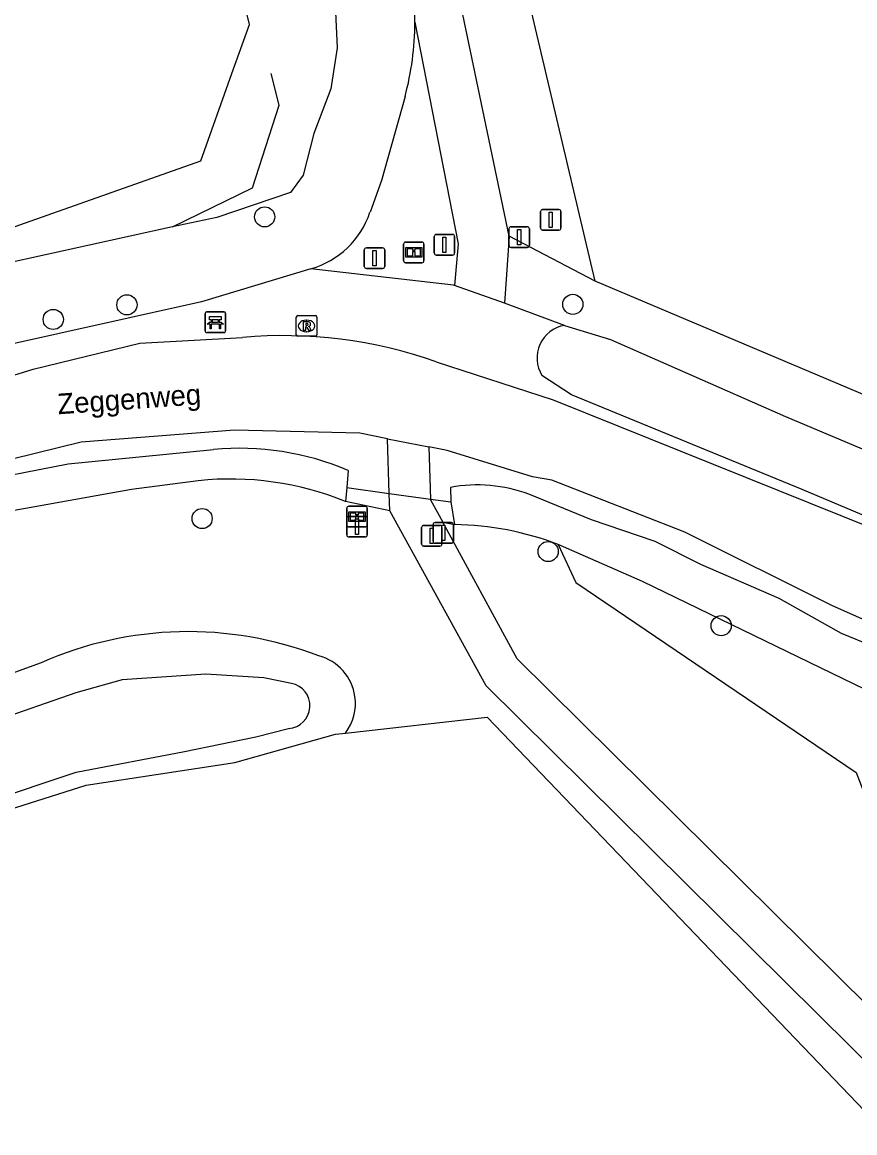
# Model space of a CAD drawing. Extents: x 164494 to 166241, y 382475 to 384494.
# Drawn here: x 164923.4 to 164963.8, y 383448.6 to 383502.5 of the extents above; entities that cross this region are included whole.
import ezdxf

# ---------------------------------------------------------------- set-up
doc = ezdxf.new("R2010")
doc.units = 0
for name, color, linetype in [('IMGEO_Afsluitpaal', 7, 'Continuous'), ('IMGEO_Bank', 7, 'Continuous'), ('IMGEO_Boom', 7, 'Continuous'), ('IMGEO_Bouwland', 7, 'Continuous'), ('IMGEO_Duiker', 7, 'Continuous'), ('IMGEO_Grasland_overig', 7, 'Continuous'), ('IMGEO_Groenvoorziening', 7, 'Continuous'), ('IMGEO_Hek', 7, 'Continuous'), ('IMGEO_Informatiebord', 7, 'Continuous'), ('IMGEO_Loofbos', 7, 'Continuous'), ('IMGEO_Openbare_ruimte_label', 7, 'Continuous'), ('IMGEO_Rijbaan_lokaal_halfverhard', 7, 'Continuous'), ('IMGEO_Rioolput', 7, 'Continuous'), ('IMGEO_Waterloop', 7, 'Continuous')]:
    doc.layers.add(name, color=color, linetype=linetype)

msp = doc.modelspace()

# ---------------------------------------------------------------- linework, layer by layer
at = {"layer": 'IMGEO_Afsluitpaal'}
for p, q in [((164948.533, 383492.504), (164948.533, 383493.304)), ((164948.533, 383493.304), (164948.533, 383492.504)), ((164948.633, 383493.404), (164949.423, 383493.404)), ((164949.423, 383493.404), (164948.633, 383493.404)), ((164949.523, 383493.304), (164949.523, 383492.504)), ((164949.523, 383492.504), (164949.523, 383493.304)), ((164946.998, 383491.666), (164946.998, 383492.466)), ((164946.998, 383492.466), (164946.998, 383491.666)), ((164947.098, 383492.566), (164947.888, 383492.566)), ((164947.888, 383492.566), (164947.098, 383492.566)), ((164947.988, 383492.466), (164947.988, 383491.666)), ((164947.988, 383491.666), (164947.988, 383492.466)), ((164949.423, 383492.404), (164948.633, 383492.404)), ((164948.633, 383492.404), (164949.423, 383492.404)), ((164943.37, 383491.294), (164943.37, 383492.094)), ((164943.37, 383492.094), (164943.37, 383491.294)), ((164943.47, 383492.194), (164944.26, 383492.194)), ((164944.26, 383492.194), (164943.47, 383492.194)), ((164944.36, 383492.094), (164944.36, 383491.294)), ((164944.36, 383491.294), (164944.36, 383492.094)), ((164939.975, 383490.643), (164939.975, 383491.443)), ((164939.975, 383491.443), (164939.975, 383490.643)), ((164940.075, 383491.543), (164940.865, 383491.543)), ((164940.865, 383491.543), (164940.075, 383491.543)), ((164940.965, 383491.443), (164940.965, 383490.643)), ((164940.965, 383490.643), (164940.965, 383491.443)), ((164947.888, 383491.566), (164947.098, 383491.566)), ((164947.098, 383491.566), (164947.888, 383491.566)), ((164944.26, 383491.194), (164943.47, 383491.194)), ((164943.47, 383491.194), (164944.26, 383491.194)), ((164940.865, 383490.543), (164940.075, 383490.543)), ((164940.075, 383490.543), (164940.865, 383490.543)), ((164939.126, 383477.607), (164939.126, 383478.407)), ((164939.126, 383478.407), (164939.126, 383477.607)), ((164939.226, 383478.507), (164940.016, 383478.507)), ((164940.016, 383478.507), (164939.226, 383478.507)), ((164940.116, 383478.407), (164940.116, 383477.607)), ((164940.116, 383477.607), (164940.116, 383478.407)), ((164942.754, 383477.165), (164942.754, 383477.965)), ((164942.754, 383477.965), (164942.754, 383477.165)), ((164942.854, 383478.065), (164943.644, 383478.065)), ((164943.644, 383478.065), (164942.854, 383478.065)), ((164943.312, 383477.305), (164943.312, 383478.105)), ((164943.312, 383478.105), (164943.312, 383477.305)), ((164943.412, 383478.205), (164944.202, 383478.205)), ((164944.202, 383478.205), (164943.412, 383478.205)), ((164943.744, 383477.965), (164943.744, 383477.165)), ((164943.744, 383477.165), (164943.744, 383477.965)), ((164944.302, 383478.105), (164944.302, 383477.305)), ((164944.302, 383477.305), (164944.302, 383478.105)), ((164940.016, 383477.507), (164939.226, 383477.507)), ((164939.226, 383477.507), (164940.016, 383477.507)), ((164943.644, 383477.065), (164942.854, 383477.065)), ((164942.854, 383477.065), (164943.644, 383477.065)), ((164944.202, 383477.205), (164943.412, 383477.205)), ((164943.412, 383477.205), (164944.202, 383477.205))]:
    msp.add_line(p, q, dxfattribs=at)
for points in [[(164948.953, 383493.279), (164949.103, 383493.279), (164949.103, 383492.529), (164948.953, 383492.529), (164948.953, 383493.279)], [(164947.418, 383492.441), (164947.568, 383492.441), (164947.568, 383491.691), (164947.418, 383491.691), (164947.418, 383492.441)], [(164943.79, 383492.069), (164943.94, 383492.069), (164943.94, 383491.319), (164943.79, 383491.319), (164943.79, 383492.069)], [(164940.395, 383491.418), (164940.545, 383491.418), (164940.545, 383490.668), (164940.395, 383490.668), (164940.395, 383491.418)], [(164939.546, 383478.382), (164939.696, 383478.382), (164939.696, 383477.632), (164939.546, 383477.632), (164939.546, 383478.382)], [(164943.174, 383477.94), (164943.324, 383477.94), (164943.324, 383477.19), (164943.174, 383477.19), (164943.174, 383477.94)], [(164943.732, 383478.08), (164943.882, 383478.08), (164943.882, 383477.33), (164943.732, 383477.33), (164943.732, 383478.08)]]:
    msp.add_lwpolyline(points, dxfattribs=at)
for centre, start, end in [((164948.633, 383493.304), 90, 180), ((164948.633, 383493.304), 90, 180), ((164949.423, 383493.304), 0, 90), ((164949.423, 383493.304), 360, 90), ((164947.098, 383492.466), 90, 180), ((164947.098, 383492.466), 90, 180), ((164947.888, 383492.466), 0, 90), ((164947.888, 383492.466), 360, 90), ((164948.633, 383492.504), 180, 270), ((164948.633, 383492.504), 180, 270), ((164949.423, 383492.504), 270, 0), ((164949.423, 383492.504), 270, 0), ((164943.47, 383492.094), 90, 180), ((164943.47, 383492.094), 90, 180), ((164944.26, 383492.094), 0, 90), ((164944.26, 383492.094), 360, 90), ((164940.075, 383491.443), 90, 180), ((164940.075, 383491.443), 90, 180), ((164940.865, 383491.443), 0, 90), ((164940.865, 383491.443), 360, 90), ((164943.47, 383491.294), 180, 270), ((164943.47, 383491.294), 180, 270), ((164944.26, 383491.294), 270, 0), ((164944.26, 383491.294), 270, 0), ((164947.098, 383491.666), 180, 270), ((164947.098, 383491.666), 180, 270), ((164947.888, 383491.666), 270, 0), ((164947.888, 383491.666), 270, 0), ((164940.075, 383490.643), 180, 270), ((164940.075, 383490.643), 180, 270), ((164940.865, 383490.643), 270, 0), ((164940.865, 383490.643), 270, 0), ((164939.226, 383478.407), 90, 180), ((164939.226, 383478.407), 90, 180), ((164940.016, 383478.407), 0, 90), ((164940.016, 383478.407), 360, 90), ((164942.854, 383477.965), 90, 180), ((164942.854, 383477.965), 90, 180), ((164943.412, 383478.105), 90, 180), ((164943.412, 383478.105), 90, 180), ((164943.644, 383477.965), 0, 90), ((164943.644, 383477.965), 360, 90), ((164944.202, 383478.105), 0, 90), ((164944.202, 383478.105), 360, 90), ((164939.226, 383477.607), 180, 270), ((164939.226, 383477.607), 180, 270), ((164940.016, 383477.607), 270, 0), ((164940.016, 383477.607), 270, 0), ((164943.412, 383477.305), 180, 270), ((164943.412, 383477.305), 180, 270), ((164944.202, 383477.305), 270, 0), ((164944.202, 383477.305), 270, 0), ((164942.854, 383477.165), 180, 270), ((164942.854, 383477.165), 180, 270), ((164943.644, 383477.165), 270, 0), ((164943.644, 383477.165), 270, 0)]:
    msp.add_arc(centre, 0.1, start, end, dxfattribs=at)
at = {"layer": 'IMGEO_Bank'}
for p, q in [((164932.241, 383487.508), (164932.241, 383488.349)), ((164932.241, 383488.349), (164932.241, 383487.508)), ((164932.316, 383488.433), (164933.157, 383488.433)), ((164933.157, 383488.433), (164932.316, 383488.433)), ((164933.241, 383488.358), (164933.241, 383487.517)), ((164933.241, 383487.517), (164933.241, 383488.358)), ((164932.938, 383487.831), (164932.545, 383487.831)), ((164932.55, 383487.939), (164932.55, 383488.045)), ((164932.594, 383488.045), (164932.594, 383487.939)), ((164932.882, 383488.051), (164932.6, 383488.051)), ((164932.6, 383487.933), (164932.882, 383487.933)), ((164932.888, 383487.939), (164932.888, 383488.045)), ((164932.932, 383488.045), (164932.932, 383487.939)), ((164933.166, 383487.433), (164932.325, 383487.433)), ((164932.325, 383487.433), (164933.166, 383487.433))]:
    msp.add_line(p, q, dxfattribs=at)
for points in [[(164932.544, 383488.051), (164932.458, 383488.051), (164932.458, 383488.212), (164933.021, 383488.212), (164933.021, 383488.051), (164932.938, 383488.051)], [(164932.488, 383487.831), (164932.346, 383487.831), (164932.458, 383487.933), (164932.544, 383487.933)], [(164932.538, 383487.824), (164932.538, 383487.617), (164932.495, 383487.617), (164932.495, 383487.824)], [(164932.938, 383487.933), (164933.021, 383487.933), (164933.133, 383487.831), (164932.994, 383487.831)], [(164932.988, 383487.824), (164932.988, 383487.617), (164932.944, 383487.617), (164932.944, 383487.824)]]:
    msp.add_lwpolyline(points, dxfattribs=at)
for centre, radius, start, end in [((164932.319, 383488.355), 0.0779, 92.4484, 184.2845), ((164932.319, 383488.355), 0.0779, 92.4484, 184.2845), ((164933.163, 383488.355), 0.0779, 2.4484, 94.2845), ((164933.163, 383488.355), 0.0779, 2.4484, 94.2845), ((164932.488, 383487.824), 0.00671, 2.8957, 87.1043), ((164932.545, 383487.824), 0.00671, 92.8957, 177.1043), ((164932.543, 383488.044), 0.00671, 2.8957, 87.1043), ((164932.543, 383487.94), 0.00671, 272.8957, 357.1043), ((164932.6, 383488.044), 0.00671, 92.8957, 177.1043), ((164932.6, 383487.94), 0.00671, 182.8957, 267.1043), ((164932.882, 383488.044), 0.00671, 2.8957, 87.1043), ((164932.882, 383487.94), 0.00671, 272.8957, 357.1043), ((164932.939, 383488.044), 0.00671, 92.8957, 177.1043), ((164932.939, 383487.94), 0.00671, 182.8957, 267.1043), ((164932.937, 383487.824), 0.00671, 2.8957, 87.1043), ((164932.994, 383487.824), 0.00671, 92.8957, 177.1043), ((164933.163, 383487.511), 0.0779, 272.4484, 4.2845), ((164933.163, 383487.511), 0.0779, 272.4484, 4.2845), ((164932.319, 383487.511), 0.0779, 182.4484, 274.2845), ((164932.319, 383487.511), 0.0779, 182.4484, 274.2845)]:
    msp.add_arc(centre, radius, start, end, dxfattribs=at)
at = {"layer": 'IMGEO_Boom'}
for centre in [(164935.137, 383493.047), (164928.449, 383488.778), (164950.1, 383488.8), (164924.872, 383488.067), (164932.1, 383478.4), (164948.9, 383476.8), (164957.3, 383473.2)]:
    msp.add_circle(centre, 0.489, dxfattribs=at)
at = {"layer": 'IMGEO_Bouwland'}
msp.add_lwpolyline([(164912.566, 383384.323), (164876.262, 383433.486), (164868.931, 383444.423), (164868.575, 383444.955), (164910.854, 383460.501), (164926.474, 383465.463), (164933.685, 383466.564), (164938.58, 383467.935), (164939.064, 383467.989)], dxfattribs=at)
at = {"layer": 'IMGEO_Duiker'}
msp.add_lwpolyline([(164939.126, 383479.906), (164941.181, 383479.625), (164943.19, 383479.35), (164944.181, 383479.214)], dxfattribs=at)
at = {"layer": 'IMGEO_Grasland_overig'}
for points in [[(164947.002, 383492.109), (164934.899, 383550.036), (164933.532, 383554.465)], [(164942.432, 383502.496), (164944.525, 383491.737), (164944.349, 383489.717)], [(164947.002, 383492.109), (164946.787, 383488.862)], [(164946.787, 383488.862), (164944.349, 383489.717)], [(164941.206, 383478.776), (164941.181, 383479.625), (164941.103, 383482.279)], [(164943.115, 383481.884), (164943.19, 383479.35), (164943.191, 383479.313), (164943.78, 383478.232)], [(164941.206, 383478.776), (164939.069, 383479.227)], [(165072.749, 383381.958), (165062.554, 383397.301), (165051.511, 383396.474), (165026.953, 383397.574), (165014.572, 383404.259), (164992.612, 383424.036), (164945.886, 383470.277), (164941.206, 383478.776)], [(165000.271, 383419.83), (164993.985, 383425.491), (164947.396, 383471.597), (164943.78, 383478.232)], [(164924.289, 383471.404), (164871.03, 383452.109), (164865.347, 383449.105)], [(164939.064, 383467.989), (164945.936, 383468.751), (164976.25, 383437.136), (164994.138, 383419.758), (165016.215, 383401.117), (165024.547, 383396.41), (165039.139, 383393.397), (165039.93, 383393.368)]]:
    msp.add_lwpolyline(points, dxfattribs=at)
for centre, radius, start, end in [((164931.425, 383455.265), 17.646, 68.9455, 113.8517), ((164937.164, 383469.428), 2.381, 8.0765, 75.4141), ((164937.16, 383469.427), 2.386, 322.9446, 8.1031)]:
    msp.add_arc(centre, radius, start, end, dxfattribs=at)
at = {"layer": 'IMGEO_Groenvoorziening'}
for points in [[(164951.182, 383489.918), (164935.814, 383555.048)], [(164951.182, 383489.918), (164947.002, 383492.109)], [(164944.349, 383489.717), (164944.305, 383489.733), (164937.381, 383490.527)], [(164993.515, 383472.033), (164951.182, 383489.918)], [(164949.691, 383487.781), (164946.787, 383488.862)], [(164943.78, 383478.232), (164944.358, 383478.11)]]:
    msp.add_lwpolyline(points, dxfattribs=at)
at = {"layer": 'IMGEO_Hek'}
for points in [[(164993.515, 383472.033), (164951.182, 383489.918), (164935.814, 383555.048), (164977.852, 383564.413), (164998.766, 383492.316), (164993.515, 383472.033)], [(164930.655, 383492.556), (164934.54, 383494.463), (164935.833, 383498.473), (164935.453, 383500)]]:
    msp.add_lwpolyline(points, dxfattribs=at)
at = {"layer": 'IMGEO_Informatiebord'}
for p, q in [((164941.882, 383490.922), (164941.882, 383491.722)), ((164941.882, 383491.722), (164941.882, 383490.922)), ((164941.982, 383491.822), (164942.772, 383491.822)), ((164942.772, 383491.822), (164941.982, 383491.822)), ((164942.872, 383491.722), (164942.872, 383490.922)), ((164942.872, 383490.922), (164942.872, 383491.722)), ((164942.772, 383490.822), (164941.982, 383490.822)), ((164941.982, 383490.822), (164942.772, 383490.822)), ((164939.126, 383478.096), (164939.126, 383478.896)), ((164939.126, 383478.896), (164939.126, 383478.096)), ((164939.226, 383478.996), (164940.016, 383478.996)), ((164940.016, 383478.996), (164939.226, 383478.996)), ((164940.116, 383478.896), (164940.116, 383478.096)), ((164940.116, 383478.096), (164940.116, 383478.896)), ((164940.016, 383477.996), (164939.226, 383477.996)), ((164939.226, 383477.996), (164940.016, 383477.996))]:
    msp.add_line(p, q, dxfattribs=at)
for points in [[(164941.983, 383491.554), (164942.771, 383491.554), (164942.771, 383491.09), (164941.983, 383491.09), (164941.983, 383491.554)], [(164942.048, 383491.489), (164942.048, 383491.155), (164942.323, 383491.155), (164942.324, 383491.368), (164942.428, 383491.369), (164942.429, 383491.155), (164942.706, 383491.155), (164942.706, 383491.489), (164942.43, 383491.489), (164942.43, 383491.409), (164942.324, 383491.409), (164942.324, 383491.489), (164942.048, 383491.489)], [(164939.227, 383478.728), (164940.015, 383478.728), (164940.015, 383478.264), (164939.227, 383478.264), (164939.227, 383478.728)], [(164939.292, 383478.663), (164939.292, 383478.329), (164939.567, 383478.329), (164939.568, 383478.542), (164939.672, 383478.543), (164939.673, 383478.329), (164939.95, 383478.329), (164939.95, 383478.663), (164939.674, 383478.663), (164939.674, 383478.583), (164939.568, 383478.583), (164939.568, 383478.663), (164939.292, 383478.663)]]:
    msp.add_lwpolyline(points, dxfattribs=at)
for centre, start, end in [((164941.982, 383491.722), 90, 180), ((164941.982, 383491.722), 90, 180), ((164942.772, 383491.722), 0, 90), ((164942.772, 383491.722), 360, 90), ((164941.982, 383490.922), 180, 270), ((164941.982, 383490.922), 180, 270), ((164942.772, 383490.922), 270, 0), ((164942.772, 383490.922), 270, 0), ((164939.226, 383478.896), 90, 180), ((164939.226, 383478.896), 90, 180), ((164940.016, 383478.896), 0, 90), ((164940.016, 383478.896), 360, 90), ((164939.226, 383478.096), 180, 270), ((164939.226, 383478.096), 180, 270), ((164940.016, 383478.096), 270, 0), ((164940.016, 383478.096), 270, 0)]:
    msp.add_arc(centre, 0.1, start, end, dxfattribs=at)
at = {"layer": 'IMGEO_Loofbos'}
for points in [[(164922.439, 383490.759), (164883.7, 383477.062), (164883.266, 383478.533), (164932.039, 383495.768), (164933.543, 383500), (164934.392, 383502.389), (164920.621, 383557.769), (164914.456, 383581.898), (164900.411, 383582.399), (164895.675, 383589.741), (164848.391, 383576.713), (164847.12, 383581.321)], [(164949.381, 383477.145), (164950.242, 383475.303), (164963.864, 383466.076), (164968.65, 383453.601), (164977.488, 383445.372), (164999.166, 383425.189), (165003.152, 383421.478)]]:
    msp.add_lwpolyline(points, dxfattribs=at)
at = {"layer": 'IMGEO_Rijbaan_lokaal_halfverhard'}
for points in [[(164846.387, 383459.64), (164853.943, 383461.373), (164860.735, 383462.825), (164865.962, 383464.299), (164869.596, 383465.427), (164878.966, 383468.472), (164900.223, 383476.754), (164908.882, 383480.203), (164916, 383483.026), (164918.976, 383484.138), (164923.891, 383485.657), (164929.074, 383486.908), (164934.056, 383487.198)], [(164943.459, 383486.014), (164949.152, 383484.161), (164964.674, 383477.923), (164974.235, 383473.548), (164981.116, 383470.331), (164985.673, 383468.365), (164993.09, 383466.489), (164999.077, 383465.148), (165005.869, 383464.88), (165016.056, 383464.076), (165027.851, 383463.629), (165033.242, 383463.929)], [(164941.103, 383482.279), (164939.754, 383482.543), (164933.677, 383482.698), (164926.219, 383482.116), (164920.619, 383480.729)], [(164941.103, 383482.279), (164943.115, 383481.884)], [(165057.829, 383459.196), (165054.68, 383459.669), (165044.405, 383460.073), (165036.169, 383460.152), (165027.707, 383460.49), (165018.059, 383460.876), (165005.712, 383461.54), (164999.222, 383461.518), (164989.292, 383463.573), (164983.35, 383465.271), (164978.428, 383467.33), (164973.989, 383469.17), (164962.708, 383474.168), (164955.538, 383477.746), (164949.085, 383480.261), (164948.146, 383480.423), (164943.99, 383481.713), (164943.115, 383481.884)]]:
    msp.add_lwpolyline(points, dxfattribs=at)
msp.add_arc((164936.018, 383464.848), 22.436, 70.6303, 95.0162, dxfattribs=at)
at = {"layer": 'IMGEO_Rioolput'}
for p, q in [((164936.67, 383487.325), (164936.67, 383488.177)), ((164936.745, 383488.251), (164937.597, 383488.251)), ((164937.671, 383488.177), (164937.671, 383487.325)), ((164937.158, 383488.031), (164937.183, 383488.031)), ((164937.597, 383487.251), (164936.745, 383487.251)), ((164937.181, 383487.471), (164937.156, 383487.471))]:
    msp.add_line(p, q, dxfattribs=at)
for points in [[(164936.67, 383487.325), (164936.67, 383488.177)], [(164936.745, 383488.251), (164937.597, 383488.251)], [(164937.671, 383488.177), (164937.671, 383487.325)], [(164937.259, 383487.949), (164937.007, 383487.951), (164937.007, 383487.551)], [(164937.007, 383487.551), (164937.131, 383487.551), (164937.131, 383487.713), (164937.142, 383487.713)], [(164937.185, 383487.87), (164937.131, 383487.87), (164937.131, 383487.789)], [(164937.131, 383487.789), (164937.183, 383487.789)], [(164937.189, 383487.684), (164937.26, 383487.551), (164937.4, 383487.551), (164937.335, 383487.677)], [(164937.597, 383487.251), (164936.745, 383487.251)]]:
    msp.add_lwpolyline(points, dxfattribs=at)
for centre, radius, start, end in [((164936.747, 383488.175), 0.0765, 91.552, 178.448), ((164936.747, 383488.175), 0.0765, 91.552, 178.448), ((164937.595, 383488.175), 0.0765, 1.552, 88.448), ((164937.595, 383488.175), 0.0765, 1.552, 88.448), ((164937.141, 383487.66), 0.0533, 26.0293, 88.6989), ((164937.167, 383487.978), 0.19, 274.7715, 282.9687), ((164937.191, 383487.774), 0.0964, 77.0061, 93.1865), ((164937.205, 383487.831), 0.0378, 276.6634, 79.6772), ((164937.258, 383487.839), 0.109, 350.3612, 89.416), ((164937.256, 383487.839), 0.112, 277.5842, 350.9817), ((164937.24, 383487.624), 0.108, 29.5134, 73.7905), ((164936.747, 383487.327), 0.0765, 181.552, 268.448), ((164936.747, 383487.327), 0.0765, 181.552, 268.448), ((164937.595, 383487.327), 0.0765, 271.552, 358.448), ((164937.595, 383487.327), 0.0765, 271.552, 358.448)]:
    msp.add_arc(centre, radius, start, end, dxfattribs=at)
for centre, major_axis, ratio, start_param, end_param in [((164937.157, 383487.751), (-0.387, 0.002), 0.722429, 4.712389, 7.853982), ((164937.182, 383487.751), (-0.39, 0.002), 0.717154, 1.570796, 4.712389)]:
    msp.add_ellipse(centre, major_axis=major_axis, ratio=ratio, start_param=start_param, end_param=end_param, dxfattribs=at)
at = {"layer": 'IMGEO_Waterloop'}
for points in [[(164917.628, 383582.827), (164919.177, 383578.107), (164923.107, 383561.975), (164927.327, 383547.127), (164933.129, 383526.073), (164937.044, 383511.773), (164938.474, 383505.068), (164938.661, 383501.255), (164938.348, 383499.27), (164937.523, 383497.092), (164936.999, 383495.076), (164936.387, 383494.227), (164932.817, 383493.02), (164930.655, 383492.556), (164922.439, 383490.759)], [(164941.953, 383498.889), (164940.813, 383494.812), (164940.251, 383493.269)], [(164937.381, 383490.527), (164932.069, 383488.924), (164921.513, 383486.57), (164916.624, 383485.254), (164907.947, 383482), (164904.766, 383480.487), (164879.529, 383470.631), (164869.248, 383466.838), (164852.63, 383462.833), (164843.612, 383461.437), (164843.123, 383461.582), (164842.523, 383461.759), (164839.074, 383465.785), (164838.555, 383466.953), (164835.287, 383473.588), (164828.161, 383491.006), (164829.882, 383491.714)], [(164949.691, 383487.781), (164951.928, 383487.088), (164960.428, 383483.359), (164965.075, 383481.391), (164971.321, 383478.456), (164979.633, 383475.127), (164988.479, 383472.046), (164993.857, 383470.444), (164995.198, 383470.01), (164996.45, 383469.322)], [(164996.45, 383469.322), (164996.738, 383468.847), (164996.597, 383468.111), (164996.116, 383467.846), (164994.631, 383467.734), (164991.391, 383468.008), (164987.266, 383468.961), (164983.358, 383470.42), (164980.247, 383471.803), (164975.569, 383473.759), (164969.135, 383476.476), (164961.235, 383479.813), (164950.04, 383484.407), (164948.6, 383485.349)], [(164857.558, 383455.915), (164857.419, 383456.458), (164857.229, 383457.202), (164860.608, 383458.332), (164870.476, 383460.687), (164880.047, 383463.612), (164886.717, 383465.911), (164905.253, 383473.685), (164906.253, 383474.343), (164909.134, 383475.436), (164911.595, 383476.59), (164920.618, 383480.089), (164925.597, 383481.057), (164932.651, 383481.754)], [(164939.195, 383480.74), (164939.126, 383479.906), (164939.069, 383479.227)], [(164931.914, 383480.237), (164928.674, 383479.81), (164922.894, 383478.784), (164919.474, 383477.792), (164911.232, 383474.851), (164901.408, 383470.314), (164898.593, 383469.326), (164887.355, 383464.67), (164880.544, 383462.211), (164871.064, 383459.446), (164857.558, 383455.915)], [(164944.155, 383479.913), (164944.181, 383479.214), (164944.358, 383478.11)], [(165060.633, 383455.796), (165060.791, 383456.334), (165061.029, 383457.622), (165050.14, 383458.419), (165038.205, 383458.867), (165030.51, 383458.886), (165027.709, 383458.765), (165025.251, 383458.659), (165019.194, 383458.853), (165011.877, 383458.85), (165000, 383459.617), (164997.719, 383459.89), (164992.054, 383460.231), (164986.153, 383461.152), (164983.635, 383461.858), (164977.999, 383465.501), (164967.239, 383470.558), (164964.643, 383472.204), (164963.145, 383472.827), (164960.11, 383474.514), (164956.314, 383476.164), (164954.094, 383477.295), (164951.001, 383478.337), (164947.97, 383479.578)], [(165040.114, 383456.721), (165036.983, 383456.91), (165032.765, 383457), (165027.711, 383456.843), (165021.429, 383456.648), (165012.533, 383456.769), (165002.418, 383457.273), (165000, 383457.515), (164992.84, 383458.067), (164987.733, 383459.039), (164983.412, 383460.239), (164966.995, 383468.798), (164953.474, 383475.351), (164949.381, 383477.145)], [(164936.435, 383470.393), (164935.094, 383470.661), (164932.28, 383470.839), (164928.214, 383470.571), (164925.96, 383469.938), (164913.965, 383465.771), (164867.624, 383448.92)], [(164910.33, 383380.925), (164911.909, 383382.143), (164905.795, 383391.218), (164868.773, 383440.664), (164867.752, 383443.303), (164867.326, 383444.749), (164868.943, 383447.047), (164874.646, 383448.92), (164925.991, 383466.081), (164931.252, 383467.086), (164934.715, 383467.812), (164936.301, 383468.215)]]:
    msp.add_lwpolyline(points, dxfattribs=at)
for centre, radius, start, end in [((164928.151, 383502.558), 14.281, 359.7502, 12.6219), ((164928.172, 383502.554), 14.26, 345.1055, 359.7655), ((164936.207, 383494.629), 4.266, 285.9719, 341.415), ((164949.972, 383486.194), 1.612, 100.0505, 211.6273), ((164933.902, 383468.201), 13.611, 67.1123, 95.2717), ((164933.479, 383465.476), 14.844, 67.8783, 96.0521), ((164945.458, 383472.864), 7.169, 69.489, 100.4743), ((164944.119, 383463.309), 14.803, 69.1763, 89.0738), ((164936.237, 383469.312), 1.099, 273.3195, 79.6392)]:
    msp.add_arc(centre, radius, start, end, dxfattribs=at)

# ---------------------------------------------------------------- texts
at = {"layer": 'IMGEO_Openbare_ruimte_label'}
msp.add_text('Zeggenweg', height=1, rotation=4.0122, dxfattribs=at).set_placement((164925.106, 383483.46))

doc.saveas('drawing.dxf')
